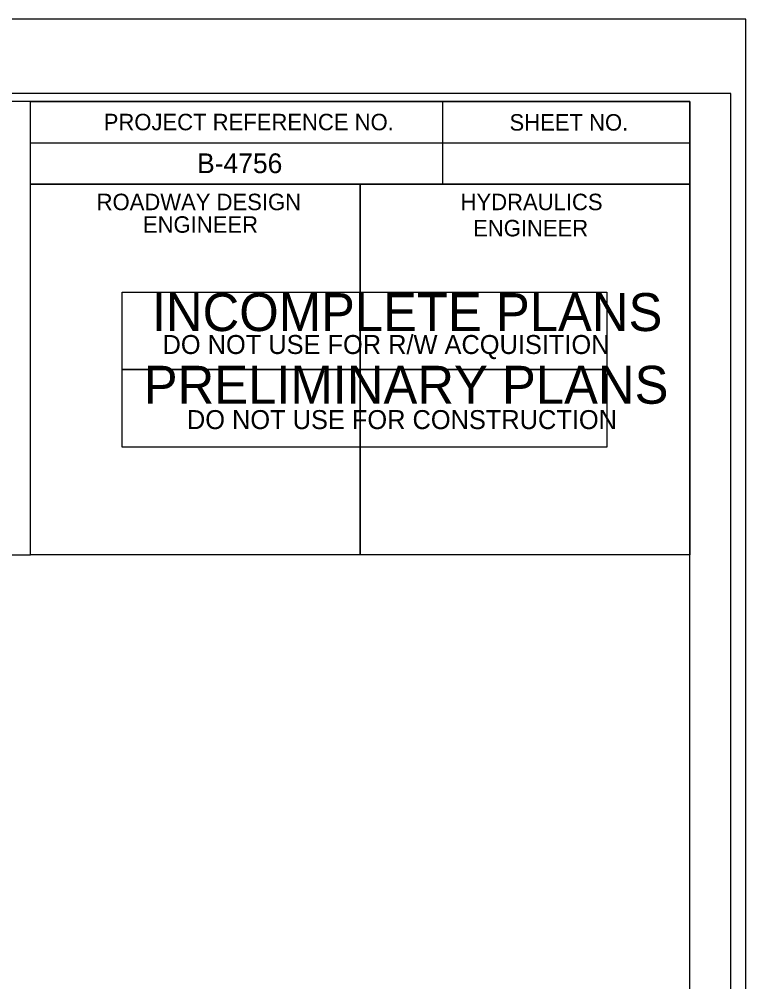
# Model space of a CAD drawing. Extents: x 2431000 to 2534000, y 645879 to 714000.
# Drawn here: x 2464298.6 to 2464519.1, y 662081.3 to 662373.5 of the extents above; entities that cross this region are included whole.
import ezdxf

# ---------------------------------------------------------------- set-up
doc = ezdxf.new("R2010")
doc.units = 0
for name, color, linetype in [('KHA_LOGO', 7, 'Continuous'), ('Sheet Plan CELL', 7, 'Continuous'), ('Sheet Plot Border Inside CELL', 7, 'Continuous'), ('Sheet Plot Border Outside CELL', 7, 'Continuous'), ('Sheet Title CELL', 7, 'Continuous'), ('Sheet Typical CELL', 7, 'Continuous')]:
    doc.layers.add(name, color=color, linetype=linetype)

msp = doc.modelspace()

# ---------------------------------------------------------------- linework, layer by layer
at = {"layer": 'KHA_LOGO'}
msp.add_lwpolyline([(2464202.02, 662210.91), (2464302.02, 662210.91), (2464302.02, 662348.46), (2464202.02, 662348.46)], close=True, dxfattribs=at)
at = {"layer": 'Sheet Plan CELL'}
for points in [[(2464302.02, 662323.36), (2464402.07, 662323.36), (2464402.07, 662210.86), (2464302.02, 662210.86)], [(2464402.07, 662323.36), (2464502.07, 662323.36), (2464502.07, 662210.86), (2464402.07, 662210.86)]]:
    msp.add_lwpolyline(points, close=True, dxfattribs=at)
at = {"layer": 'Sheet Plot Border Inside CELL'}
msp.add_lwpolyline([(2462848.57, 661295.96), (2464514.57, 661295.96), (2464514.57, 662350.96), (2462848.57, 662350.96)], close=True, dxfattribs=at)
at = {"layer": 'Sheet Plot Border Outside CELL'}
msp.add_lwpolyline([(2462835.57, 661273.46), (2464519.07, 661273.46), (2464519.07, 662373.46), (2462835.57, 662373.46)], close=True, dxfattribs=at)
at = {"layer": 'Sheet Title CELL'}
for points in [[(2464329.87, 662267.11), (2464329.87, 662290.61), (2464476.87, 662290.61), (2464476.87, 662267.12)], [(2464329.87, 662243.62), (2464329.87, 662267.11), (2464476.87, 662267.12), (2464476.87, 662243.62)]]:
    msp.add_lwpolyline(points, close=True, dxfattribs=at)
at = {"layer": 'Sheet Typical CELL'}
for p, q in [((2464427.07, 662348.41), (2464427.07, 662323.41)), ((2464302.02, 662335.91), (2464502.07, 662335.91))]:
    msp.add_line(p, q, dxfattribs=at)
for points in [[(2464502.07, 662348.46), (2463002.07, 662348.46), (2463002.07, 661298.46), (2464502.07, 661298.46)], [(2464302.02, 662348.46), (2464502.07, 662348.46), (2464502.07, 662323.41), (2464302.02, 662323.41)]]:
    msp.add_lwpolyline(points, close=True, dxfattribs=at)

# ---------------------------------------------------------------- texts
at = {"layer": 'Sheet Plan CELL'}
for s, height, p in [('B-4756', 6, (2464352.56, 662326.75)), ('HYDRAULICS', 5, (2464432.52, 662315.51)), ('ENGINEER', 5, (2464436.32, 662307.56))]:
    msp.add_text(s, height=height, dxfattribs=at).set_placement(p)
at = {"layer": 'Sheet Title CELL'}
for s, height, p in [('INCOMPLETE PLANS', 11.52, (2464338.82, 662278.82)), ('DO NOT USE FOR R/W ACQUISITION', 5.76, (2464342.07, 662271.86)), ('PRELIMINARY PLANS', 11.52, (2464336.37, 662256.76)), ('DO NOT USE FOR CONSTRUCTION', 5.76, (2464349.47, 662249.07))]:
    msp.add_text(s, height=height, dxfattribs=at).set_placement(p)
at = {"layer": 'Sheet Typical CELL'}
for s, height, p in [('PROJECT REFERENCE NO.', 5.0001, (2464324.22, 662339.76)), ('SHEET NO.', 5, (2464447.37, 662339.66)), ('ROADWAY DESIGN', 5.0001, (2464322.07, 662315.51)), ('ENGINEER', 5, (2464336.12, 662308.66))]:
    msp.add_text(s, height=height, dxfattribs=at).set_placement(p)

doc.saveas('drawing.dxf')
